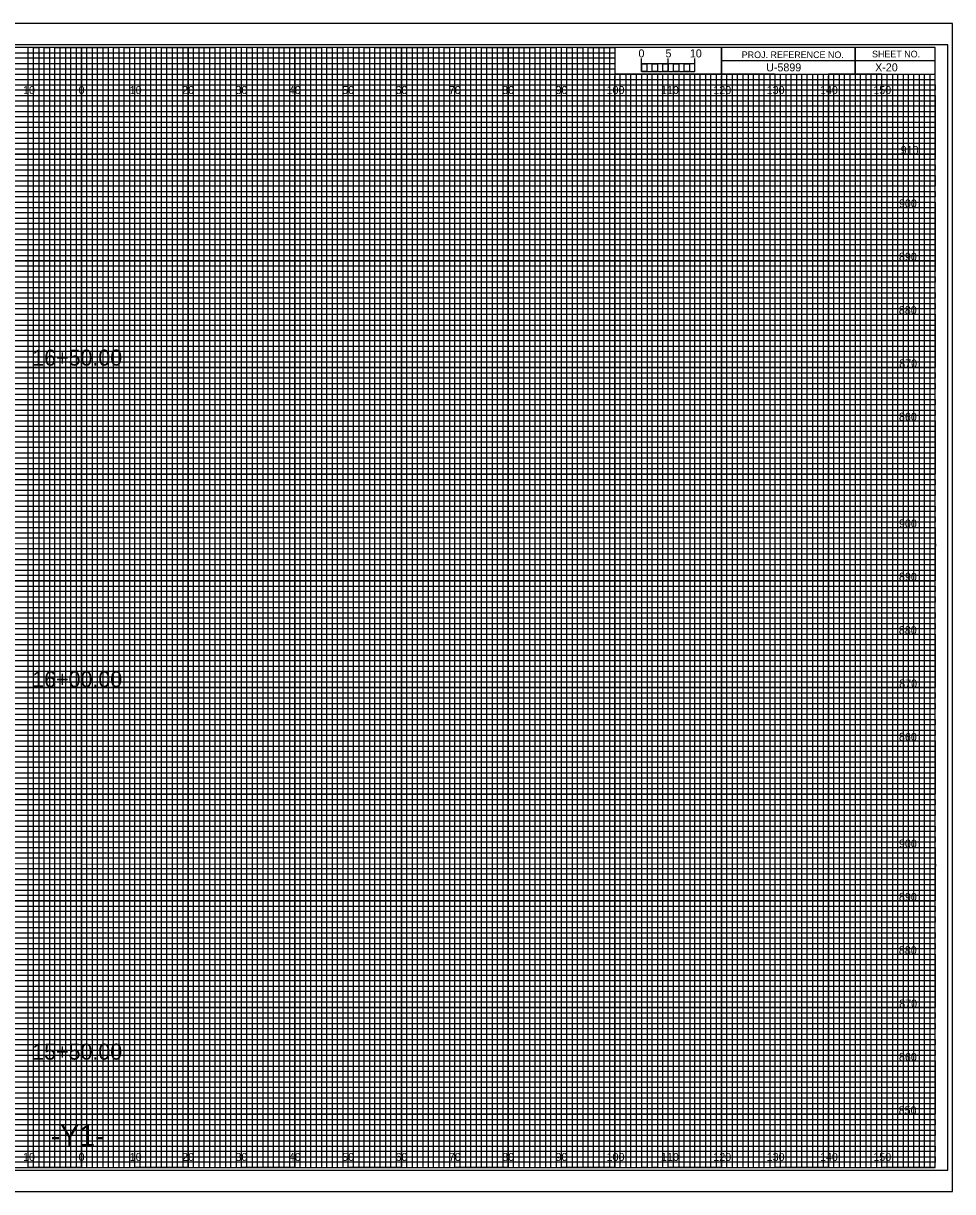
# Model space of a CAD drawing. Extents: x -13 to 323, y 876 to 1094.
# Drawn here: x 149.1 to 323.3, y 875.5 to 1094.5 of the extents above; entities that cross this region are included whole.
import ezdxf

# ---------------------------------------------------------------- set-up
doc = ezdxf.new("R2010")
doc.units = 0
for name, color, linetype in [('Prop XS Alignment Label', 7, 'Continuous'), ('Prop XS Bar Scale Labels', 7, 'Continuous'), ('Prop XS Elevation Labels', 7, 'Continuous'), ('Prop XS Project Number', 7, 'Continuous'), ('Prop XS Shear Point Element', 7, 'Continuous'), ('Prop XS Sheet Number', 7, 'Continuous'), ('Prop XS Station Labels', 7, 'Continuous'), ('Scratch_Level_4', 7, 'Continuous'), ('Sheet Cross Section CELL', 7, 'Continuous'), ('Sheet Cross Section Grid Middle CELL', 7, 'Continuous'), ('Sheet Cross Section Grid Minor 1 CELL', 7, 'Continuous'), ('Sheet Cross Section Grid Minor 2 CELL', 7, 'Continuous'), ('Sheet Cross Section Scale CELL', 7, 'Continuous'), ('Sheet Cutting Line CELL', 7, 'Continuous'), ('Sheet DOT Grid CELL', 7, 'Continuous'), ('Sheet Plot Border Inside CELL', 7, 'Continuous'), ('Sheet Plot Border Outside CELL', 7, 'Continuous')]:
    doc.layers.add(name, color=color, linetype=linetype)

msp = doc.modelspace()

# ---------------------------------------------------------------- linework, layer by layer
at = {"layer": 'Scratch_Level_4'}
for p, q in [((150, 1090), (140, 1090)), ((150, 880), (150, 1090)), ((170, 1090), (160, 1090)), ((160, 1090), (160, 880)), ((170, 880), (170, 1090)), ((190, 1090), (180, 1090)), ((180, 1090), (180, 880)), ((190, 880), (190, 1090)), ((210, 1090), (200, 1090)), ((200, 1090), (200, 880)), ((210, 880), (210, 1090)), ((230, 1090), (220, 1090)), ((220, 1090), (220, 880)), ((230, 880), (230, 1090)), ((250, 1090), (240, 1090)), ((240, 1090), (240, 880)), ((250, 880), (250, 1090)), ((260, 1090), (260, 880)), ((270, 880), (270, 1085)), ((290, 1085), (280, 1085)), ((280, 1085), (280, 880)), ((290, 880), (290, 1085)), ((310, 1085), (300, 1085)), ((300, 1085), (300, 880)), ((310, 880), (310, 1085)), ((160, 880), (150, 880)), ((180, 880), (170, 880)), ((200, 880), (190, 880)), ((220, 880), (210, 880)), ((240, 880), (230, 880)), ((260, 880), (250, 880)), ((280, 880), (270, 880)), ((300, 880), (290, 880)), ((320, 880), (310, 880)), ((320, 880), (320, 880))]:
    msp.add_line(p, q, dxfattribs=at)
for points in [[(0, 1080), (320, 1080), (320, 1070), (0, 1070)], [(0, 1060), (320, 1060), (320, 1050), (0, 1050)], [(0, 1040), (320, 1040), (320, 1030), (0, 1030)], [(0, 1020), (320, 1020), (320, 1010), (0, 1010)], [(0, 1000), (320, 1000), (320, 990), (0, 990)], [(0, 980), (320, 980), (320, 970), (0, 970)], [(0, 960), (320, 960), (320, 950), (0, 950)], [(0, 940), (320, 940), (320, 930), (0, 930)], [(0, 920), (320, 920), (320, 910), (0, 910)], [(0, 900), (320, 900), (320, 890), (0, 890)]]:
    msp.add_lwpolyline(points, dxfattribs=at)
at = {"layer": 'Sheet Cross Section CELL'}
for p, q in [((305, 1090), (305, 1085)), ((305, 1085), (305, 1090)), ((280, 1087.5), (280, 1085)), ((320, 1087.49), (280, 1087.49)), ((280, 1085), (320, 1085))]:
    msp.add_line(p, q, dxfattribs=at)
for points in [[(320, 1090), (0, 1090), (0, 880), (320, 880)], [(280, 1090), (260, 1090), (260, 1085.03), (280, 1085.03)], [(320, 1090), (280, 1090), (280, 1085), (320, 1085)]]:
    msp.add_lwpolyline(points, close=True, dxfattribs=at)
at = {"layer": 'Sheet Cross Section Grid Middle CELL'}
for points in [[(145, 880), (155, 880), (155, 1090), (165, 1090), (165, 880), (175, 880), (175, 1090), (185, 1090), (185, 880), (195, 880), (195, 1090), (205, 1090), (205, 880), (215, 880), (215, 1090), (225, 1090), (225, 880), (235, 880), (235, 1090), (245, 1090), (245, 880), (255, 880), (255, 1090), (259.93, 1090), (260, 1090), (260, 1085), (264.99, 1085), (264.99, 880), (275, 880), (275, 1085), (285, 1085), (285, 880), (295, 880), (295, 1085), (305, 1085), (305, 880), (315, 880), (315, 1085)], [(0, 1085), (275, 1085)], [(0, 1065), (320, 1065), (320, 1075), (0, 1075)], [(0, 1045), (320, 1045), (320, 1055), (0, 1055)], [(0, 1025), (320, 1025), (320, 1035), (0, 1035)], [(0, 1005), (320, 1005), (320, 1015), (0, 1015)], [(0, 985), (320, 985), (320, 995), (0, 995)], [(0, 965), (320, 965), (320, 975), (0, 975)], [(0, 945), (320, 945), (320, 955), (0, 955)], [(0, 925), (320, 925), (320, 935), (0, 935)], [(0, 905), (320, 905), (320, 915), (0, 915)], [(0, 885), (320, 885), (320, 895), (0, 895)]]:
    msp.add_lwpolyline(points, dxfattribs=at)
at = {"layer": 'Sheet Cross Section Grid Minor 1 CELL'}
for p, q in [((0, 1089), (260, 1089)), ((260, 1089), (260, 1087.98)), ((260, 1087.98), (0, 1087.98)), ((0, 1087), (260, 1087)), ((260, 1087), (260, 1085.89)), ((260, 1085.89), (0, 1085.89)), ((0, 1084), (320, 1084))]:
    msp.add_line(p, q, dxfattribs=at)
for points in [[(0, 1083), (270, 1083), (320, 1083), (320, 1082), (0, 1082)], [(0, 1081), (320, 1081), (320, 1079), (0, 1079)], [(0, 1078), (320, 1078), (320, 1077), (0, 1076.98)], [(0, 1076), (320, 1076), (320, 1074), (0, 1074)], [(0, 1073), (320, 1073), (320, 1072), (0, 1072)], [(0, 1071), (320, 1071), (320, 1069), (0, 1069)], [(0, 1068), (320, 1068), (320, 1067), (0, 1067)], [(0, 1066), (320, 1066), (320, 1064), (0, 1064)], [(0, 1063), (320, 1063), (320, 1062), (0, 1062)], [(0, 1061), (320, 1061), (320, 1059), (0, 1059)], [(0, 1058), (320, 1058), (320, 1057), (0, 1057)], [(0, 1056), (320, 1056), (320, 1053.95), (320, 1053), (320, 1052), (0, 1052)], [(0, 1054), (320, 1054), (320, 1053), (0, 1053)], [(0, 1051), (320, 1051), (320, 1049), (0, 1049.03)], [(0, 1049.03), (320, 1049), (320, 1048), (0, 1048)], [(0, 1047), (320, 1047), (320, 1046), (0, 1046)], [(0, 1044), (320, 1044), (320, 1043), (0, 1043)], [(0, 1042), (320, 1042), (320, 1041), (0, 1041)], [(-0.07, 1038.89), (320, 1038.89), (320, 1037.88), (-0.07, 1037.88)], [(0, 1037), (320, 1037), (320, 1036), (0, 1036)], [(0, 1034), (320, 1034), (320, 1033), (0, 1033)], [(0, 1032), (320, 1032), (320, 1031), (0, 1031)], [(0, 1029), (320, 1029), (320, 1028), (0, 1028)], [(0, 1027), (320, 1027), (320, 1026), (0, 1026)], [(0, 1024), (320, 1024), (320, 1023), (0, 1023)], [(0, 1022), (320, 1022), (320, 1021), (0, 1021)], [(0, 1019), (320, 1019), (319.99, 1017.98), (0, 1018)], [(0, 1017), (320, 1017), (320, 1016), (0, 1016)], [(0, 1014), (320, 1014), (320, 1013), (0, 1013)], [(0, 1012), (320, 1012), (320, 1011), (0, 1011)], [(0, 1009), (320, 1009), (320, 1008), (0, 1008)], [(0, 1007), (320, 1007), (320, 1006), (0, 1006)], [(0, 1004), (320, 1004), (320, 1003), (0, 1003)], [(0, 1002), (320, 1002), (320, 1001), (0, 1001)], [(0, 999), (320, 999), (320, 998), (0, 998)], [(0, 996.99), (320.07, 996.91), (320, 996), (0, 996)], [(0, 994), (320, 994), (320, 993), (0, 993)], [(0, 992), (320, 992), (320, 991), (0, 991)], [(0, 989), (320, 989), (320, 988), (0, 988)], [(0, 987), (320, 987), (320, 986), (0, 986)], [(0, 984), (320, 984), (320, 983), (0, 983)], [(0, 982), (320, 982), (320, 981), (0, 981)], [(0, 979), (320, 979), (320, 978), (0, 978)], [(0, 977), (320, 977), (320, 976), (0, 976)], [(0, 974), (320, 974), (320, 973), (0, 973)], [(0, 972), (320, 972), (320, 971), (0, 971)], [(0, 969), (320, 969), (320, 968), (0, 968)], [(0, 967), (320, 967), (320, 966), (0, 966)], [(0, 964), (320, 964), (320, 963), (0, 963)], [(0, 962), (320, 962), (320, 961), (0, 961)], [(0, 959), (320, 959), (319.99, 957.98), (0, 958)], [(0, 957), (320, 957), (320, 956), (0, 956)], [(0, 954), (320, 954), (320, 953), (0, 953)], [(0, 952), (320, 952), (320, 951), (0, 951)], [(0, 949), (320, 949), (320, 948), (0, 948)], [(0, 947), (320, 947), (320, 946), (0, 946)], [(0, 944), (320, 944), (320, 943), (0, 943)], [(0, 942), (320, 942), (320, 941), (0, 941)], [(0, 939), (320, 939), (320, 938), (0, 938)], [(0, 936.99), (320.07, 936.91), (320, 936), (0, 936)], [(0, 934), (320, 934), (320, 933), (0, 933)], [(0, 932), (320, 932), (320, 931), (0, 931)], [(0, 929), (320, 929), (320, 928), (0, 928)], [(0, 927), (320, 927), (320, 926), (0, 926)], [(0, 924), (320, 924), (320, 923), (0, 923)], [(0, 922), (320, 922), (320, 921), (0, 921)], [(0, 919), (320, 919), (320, 918), (0, 918)], [(0, 917), (320, 917), (320, 916), (0, 916)], [(0, 914), (320, 914), (320, 913), (0, 913)], [(0, 912), (320, 912), (320, 911), (0, 911)], [(0, 909), (320, 909), (320, 908), (0, 908)], [(0, 907), (320, 907), (320, 906), (0, 906)], [(0, 904), (320, 904), (320, 903), (0, 903)], [(0, 902), (320, 902), (320, 901), (0, 901)], [(0, 899), (320, 899), (320, 898), (0, 898)], [(0, 897), (320, 897), (320, 896), (0, 896)], [(0, 894), (320, 894), (320, 893), (0, 893)], [(0, 892), (320, 892), (320, 891), (0, 891)], [(0, 889), (320, 889), (320, 888), (0, 888)], [(0, 887), (320, 887), (320, 886), (0, 886)], [(0, 884), (320, 884), (320, 883), (0, 883)], [(0, 882), (320, 882), (320, 881), (0, 881)]]:
    msp.add_lwpolyline(points, dxfattribs=at)
at = {"layer": 'Sheet Cross Section Grid Minor 2 CELL'}
for p, q in [((267, 1085), (266.01, 1085)), ((266.01, 1085), (266.01, 880)), ((267, 880), (267, 1085)), ((269, 1085), (268, 1085)), ((268, 1085), (268, 880)), ((269, 880), (269, 1085)), ((266.01, 880), (265, 880)), ((268, 880), (267, 880))]:
    msp.add_line(p, q, dxfattribs=at)
for points in [[(150, 880), (151, 880), (151, 1090), (152, 1090), (152, 880)], [(152, 880), (153, 880), (153, 1090), (154, 1090), (154, 880)], [(155, 880), (156, 880), (156, 1090), (157, 1090), (157, 880)], [(157, 880), (158, 880), (158, 1090), (159, 1090), (159, 880)], [(160, 880), (161, 880), (161, 1090), (162, 1090), (162, 880)], [(162, 880), (163, 880), (163, 1090), (164, 1090), (164, 880)], [(165, 880), (166, 880), (166, 1090), (167, 1090), (167, 880)], [(167, 880), (168, 880), (168, 1090), (169, 1090), (169, 880)], [(170, 880), (171, 880), (171, 1090), (172, 1090), (172, 880)], [(172, 880), (173, 880), (173, 1090), (174, 1090), (174, 880)], [(175, 880), (176, 880), (176, 1090), (177, 1090), (177, 880)], [(177, 880), (178, 880), (178, 1090), (179, 1090), (179, 880)], [(180, 880), (181, 880), (181, 1090), (182, 1090), (182, 880)], [(182, 880), (183, 880), (183, 1090), (184, 1090), (184, 880)], [(185, 880), (186, 880), (186, 1090), (187, 1090), (187, 880)], [(187, 880), (188, 880), (188, 1090), (189, 1090), (189, 880)], [(190, 880), (191, 880), (191, 1090), (192, 1090), (192, 880)], [(192, 880), (193, 880), (193, 1090), (194, 1090), (194, 880)], [(195, 880), (196, 880), (196, 1090), (197, 1090), (197, 880)], [(197, 880), (198, 880), (198, 1090), (199, 1090), (199, 880)], [(200, 880), (201, 880), (201, 1090), (202, 1090), (202, 880)], [(202, 880), (203, 880), (203, 1090), (204, 1090), (204, 880)], [(205, 880), (206, 880), (206, 1090), (207, 1090), (207, 880)], [(207, 880), (208, 880), (208, 1090), (209, 1090), (209, 880)], [(210, 880), (211, 880), (211, 1090), (212, 1090), (212, 880)], [(212, 880), (213, 880), (213, 1090), (214, 1090), (214, 880)], [(215, 880), (216, 880), (216, 1090), (217, 1090), (217, 880)], [(217, 880), (218, 880), (218, 1090), (219, 1090), (219, 880)], [(220, 880), (221, 880), (221, 1090), (222, 1090), (222, 880)], [(222, 880), (223, 880), (223, 1090), (224, 1090), (224, 880)], [(225, 880), (226, 880), (226, 1090), (227, 1090), (227, 880)], [(227, 880), (228, 880), (228, 1090), (229, 1090), (229, 880)], [(230, 880), (231, 880), (231, 1090), (232, 1090), (232, 880)], [(232, 880), (233, 880), (233, 1090), (234, 1090), (234, 880)], [(235, 880), (236, 880), (236, 1090), (237, 1090), (237, 880)], [(237, 880), (238, 880), (238, 1090), (239, 1090), (239, 880)], [(240, 880), (241, 880), (241, 1090), (242, 1090), (242, 880)], [(242, 880), (243, 880), (243, 1090), (244, 1090), (244, 880)], [(245, 880), (246, 880), (246, 1090), (247, 1090), (247, 880)], [(247, 880), (248, 880), (248, 1090), (249, 1090), (249, 880)], [(250, 880), (251, 880), (251, 1090), (252, 1090), (252, 880)], [(252, 880), (253, 880), (253, 1090), (254, 1090), (254, 880)], [(255, 880), (256, 880), (256, 1090), (257, 1090), (257, 880)], [(257, 880), (258, 880), (258, 1090), (259, 1090), (259, 880)], [(260, 880), (261, 880), (261, 1085), (262.02, 1085), (262.02, 880)], [(262, 880), (263, 880), (263, 1085), (263.99, 1085), (263.99, 880)], [(270, 880), (270.98, 880), (270.98, 1085), (272, 1085), (272, 880)], [(272, 880), (273, 880), (273, 1085), (274.05, 1085), (274.05, 880)], [(275, 880), (276, 880), (276, 1085), (277, 1085), (277, 880)], [(277, 880), (278, 880), (278, 1085), (279, 1085), (279, 880)], [(280, 880), (281, 880), (281, 1085), (282, 1085), (282, 880)], [(282, 880), (283, 880), (283, 1085), (284, 1085), (284, 880)], [(285, 880), (286, 880), (286, 1085), (287, 1085), (287, 880)], [(287, 880), (288, 880), (288, 1085), (289, 1085), (289, 880)], [(290, 880), (291, 880), (291, 1085), (292, 1085), (292, 880)], [(292, 880), (293, 880), (293, 1085), (294, 1085), (294, 880)], [(295, 880), (296, 880), (296, 1085), (297, 1085), (297, 880)], [(297, 880), (298, 880), (298, 1085), (299, 1085), (299, 880)], [(300, 880), (301, 880), (301, 1085), (302, 1085), (302, 880)], [(302, 880), (303, 880), (303, 1085), (304, 1085), (304, 880)], [(305, 880), (306, 880), (306, 1085), (307, 1085), (307, 880)], [(307, 880), (308, 880), (308, 1085), (309, 1085), (309, 880)], [(310, 880), (311, 880), (311, 1085), (312, 1085), (312, 880)], [(312, 880), (313, 880), (313, 1085), (314, 1085), (314, 880)], [(315, 880), (316, 880), (316, 1085), (317, 1085), (317, 880)], [(317, 880), (318, 880), (318, 1085), (319, 1085), (319, 880)]]:
    msp.add_lwpolyline(points, dxfattribs=at)
at = {"layer": 'Sheet Cross Section Scale CELL'}
for p, q in [((265, 1085.49), (265, 1087.9)), ((265, 1086.9), (265, 1087.9)), ((270, 1085.49), (270, 1087.9)), ((275, 1085.49), (275, 1087.9)), ((275, 1086.9), (275, 1087.9))]:
    msp.add_line(p, q, dxfattribs=at)
for points in [[(275, 1086.9), (265, 1086.9), (265, 1085.49), (275, 1085.49)], [(265, 1086.9), (266, 1086.9), (266, 1085.49), (265, 1085.49)], [(267, 1086.9), (268, 1086.9), (268, 1085.49), (267, 1085.49)], [(269, 1086.9), (270, 1086.9), (270, 1085.49), (269, 1085.49)], [(271, 1086.9), (272, 1086.9), (272, 1085.49), (271, 1085.49)], [(273, 1086.9), (274, 1086.9), (274, 1085.49), (273, 1085.49)]]:
    msp.add_lwpolyline(points, close=True, dxfattribs=at)
at = {"layer": 'Sheet Cutting Line CELL'}
for p, q in [((323.3, 1094.5), (-13.4, 1094.5)), ((-13.4, 875.5), (323.3, 875.5))]:
    msp.add_line(p, q, dxfattribs=at)
at = {"layer": 'Sheet DOT Grid CELL'}
for p, q in [((150, 880), (150, 1090)), ((160, 880), (160, 1090)), ((170, 880), (170, 1090)), ((180, 880), (180, 1090)), ((190, 880), (190, 1090)), ((200, 880), (200, 1090)), ((210, 880), (210, 1090)), ((220, 880), (220, 1090)), ((230, 880), (230, 1090)), ((240, 880), (240, 1090)), ((250, 880), (250, 1090)), ((260, 880), (260, 1084.69)), ((270, 880), (270, 1084.69)), ((280, 880), (280, 1084.69)), ((290, 880), (290, 1084.69)), ((300, 880), (300, 1084.69)), ((310, 880), (310, 1084.69)), ((0, 1080), (320, 1080)), ((0, 1070), (320, 1070)), ((0, 1060), (320, 1060)), ((0, 1050), (320, 1050)), ((0, 1040), (320, 1040)), ((0, 1030), (320, 1030)), ((0, 1020), (320, 1020)), ((0, 1010), (320, 1010)), ((0, 1000), (320, 1000)), ((0, 990), (320, 990)), ((0, 980), (320, 980)), ((0, 970), (320, 970)), ((0, 960), (320, 960)), ((0, 950), (320, 950)), ((0, 940), (320, 940)), ((0, 930), (320, 930)), ((0, 920), (320, 920)), ((0, 910), (320, 910)), ((0, 900), (320, 900)), ((0, 890), (320, 890))]:
    msp.add_line(p, q, dxfattribs=at)
at = {"layer": 'Sheet Plot Border Inside CELL'}
msp.add_lwpolyline([(-10.8, 879.5), (322.4, 879.5), (322.4, 1090.5), (-10.8, 1090.5)], close=True, dxfattribs=at)
at = {"layer": 'Sheet Plot Border Outside CELL'}
msp.add_lwpolyline([(-13.4, 875.5), (323.3, 875.5), (323.3, 1094.5), (-13.4, 1094.5)], close=True, dxfattribs=at)

# ---------------------------------------------------------------- texts
at = {"layer": 'Prop XS Alignment Label'}
msp.add_text('-Y1-', height=4, dxfattribs=at).set_placement((154.21, 884))
at = {"layer": 'Prop XS Bar Scale Labels'}
for s, p in [('5', (269.47, 1088.12)), ('10', (274.04, 1088.12))]:
    msp.add_text(s, height=1.5, dxfattribs=at).set_placement(p)
at = {"layer": 'Prop XS Elevation Labels'}
for s, p in [('910', (313.57, 1070)), ('900', (313.24, 1060)), ('890', (313.24, 1050)), ('880', (313.22, 1040)), ('870', (313.28, 1030)), ('860', (313.24, 1020)), ('900', (313.24, 1000)), ('890', (313.24, 990)), ('880', (313.22, 980)), ('870', (313.28, 970)), ('860', (313.24, 960)), ('900', (313.24, 940)), ('890', (313.24, 930)), ('880', (313.22, 920)), ('870', (313.28, 910)), ('860', (313.24, 900)), ('850', (313.19, 890))]:
    msp.add_text(s, height=1.5, dxfattribs=at).set_placement(p)
at = {"layer": 'Prop XS Project Number'}
msp.add_text('U-5899', height=1.5, dxfattribs=at).set_placement((288.34, 1085.5))
at = {"layer": 'Prop XS Shear Point Element'}
for s, p in [('10', (149.04, 1081.25)), ('0', (159.45, 1081.25)), ('0', (159.45, 1081.25)), ('10', (169.04, 1081.25)), ('20', (178.86, 1081.25)), ('30', (188.86, 1081.25)), ('40', (198.86, 1081.25)), ('50', (208.86, 1081.25)), ('60', (218.86, 1081.25)), ('70', (228.86, 1081.25)), ('80', (238.86, 1081.25)), ('90', (248.86, 1081.25)), ('100', (258.44, 1081.25)), ('110', (268.62, 1081.25)), ('120', (278.44, 1081.25)), ('130', (288.44, 1081.25)), ('140', (298.44, 1081.25)), ('150', (308.44, 1081.25)), ('10', (149.04, 881.25)), ('0', (159.45, 881.25)), ('0', (159.45, 881.25)), ('10', (169.04, 881.25)), ('20', (178.86, 881.25)), ('30', (188.86, 881.25)), ('40', (198.86, 881.25)), ('50', (208.86, 881.25)), ('60', (218.86, 881.25)), ('70', (228.86, 881.25)), ('80', (238.86, 881.25)), ('90', (248.86, 881.25)), ('100', (258.44, 881.25)), ('110', (268.62, 881.25)), ('120', (278.44, 881.25)), ('130', (288.44, 881.25)), ('140', (298.44, 881.25)), ('150', (308.44, 881.25))]:
    msp.add_text(s, height=1.5, dxfattribs=at).set_placement(p)
at = {"layer": 'Prop XS Sheet Number'}
msp.add_text('X-20', height=1.5, dxfattribs=at).set_placement((308.77, 1085.5))
at = {"layer": 'Prop XS Station Labels'}
for s, p in [('16+50.00', (150.77, 1030.34)), ('16+00.00', (150.77, 970.06)), ('15+50.00', (150.77, 900.24))]:
    msp.add_text(s, height=3, dxfattribs=at).set_placement(p)
at = {"layer": 'Sheet Cross Section CELL'}
for s, p in [('PROJ. REFERENCE NO.', (283.77, 1087.99)), ('SHEET NO.', (308.19, 1088.12))]:
    msp.add_text(s, height=1.25, dxfattribs=at).set_placement(p)
at = {"layer": 'Sheet Cross Section Scale CELL'}
msp.add_text('0', height=1.5, dxfattribs=at).set_placement((264.41, 1088.12))

doc.saveas('drawing.dxf')
